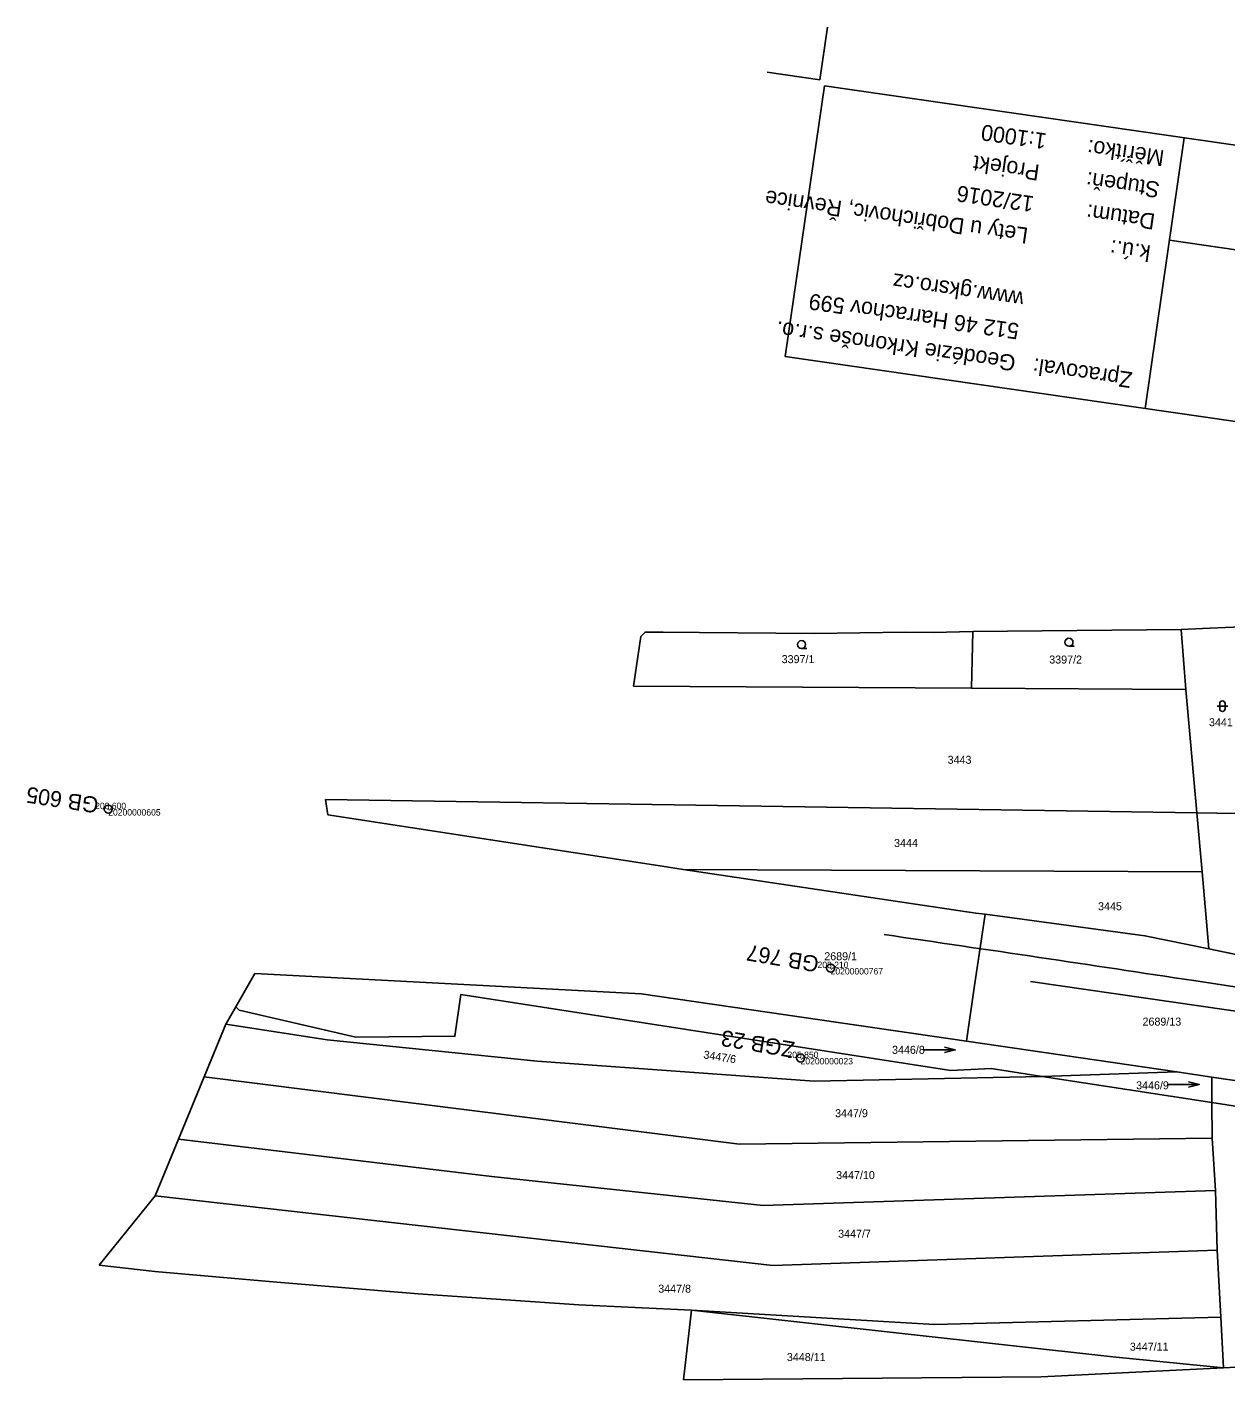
# Model space of a CAD drawing. Extents: x -757909 to -757266, y -1060303 to -1059942.
# Drawn here: x -757908.7 to -757684, y -1060195.2 to -1059941.6 of the extents above; entities that cross this region are included whole.
import ezdxf

# ---------------------------------------------------------------- set-up
doc = ezdxf.new("R2010")
doc.units = 0
for name, color, linetype in [('Legenda 1', 7, 'Continuous'), ('Vrstva 1', 7, 'Continuous'), ('Vrstva 53', 7, 'Continuous'), ('Vrstva 55', 7, 'Continuous'), ('Vrstva 57', 7, 'Continuous'), ('Vrstva 58', 7, 'Continuous'), ('Vrstva 60', 7, 'Continuous'), ('Vrstva 61', 7, 'Continuous'), ('Vrstva 63', 7, 'Continuous')]:
    doc.layers.add(name, color=color, linetype=linetype)

msp = doc.modelspace()

# ---------------------------------------------------------------- linework, layer by layer
at = {"layer": 'Legenda 1'}
for p, q in [((-757758.65, -1059941.6), (-757760.08, -1059951.5)), ((-757769.98, -1059950.07), (-757760.08, -1059951.5)), ((-757691.8, -1059962.36), (-757699.12, -1060013.09)), ((-757694.57, -1059981.56), (-757587.21, -1059997.05))]:
    msp.add_line(p, q, dxfattribs=at)
msp.add_lwpolyline([(-757759.23, -1059952.63), (-757584.43, -1059977.86), (-757591.76, -1060028.59), (-757766.56, -1060003.36)], close=True, dxfattribs=at)
at = {"layer": 'Vrstva 1'}
for p, q in [((-757429.32, -1060162.53), (-757720.62, -1060120.47)), ((-757665.26, -1060124.05), (-757689.98, -1060120.32))]:
    msp.add_line(p, q, dxfattribs=at)
msp.add_arc((-759559.14, -1072479.78), 12500, 81.400126, 81.669213, dxfattribs=at)
at = {"layer": 'Vrstva 53'}
for points in [[(-757852.31, -1060089.26), (-757789.66, -1060098.89), (-757785.7, -1060099.48), (-757730.83, -1060107.66), (-757729.12, -1060107.89), (-757699.16, -1060111.9), (-757687.19, -1060114.38), (-757639.93, -1060124.17), (-757624.54, -1060126.42), (-757624.32, -1060124.22), (-757612.89, -1060124.84), (-757606.63, -1060125.23), (-757568.62, -1060130.44), (-757535.86, -1060133.35), (-757534.03, -1060136.19), (-757533.01, -1060136.32), (-757528.28, -1060137.03), (-757525.99, -1060137.35), (-757523.49, -1060137.59)], [(-757328.56, -1060183.46), (-757338.29, -1060184.85), (-757361.91, -1060181.63), (-757443.58, -1060171.99), (-757470.38, -1060167.04), (-757513.1, -1060164.5), (-757526.21, -1060162.71), (-757533.6, -1060161.43), (-757535.01, -1060161.18), (-757542.9, -1060160.49), (-757543.88, -1060160.4), (-757632.1, -1060146.3), (-757634.26, -1060145.96), (-757635.44, -1060145.86), (-757686.64, -1060138.39), (-757693.18, -1060137.43), (-757732.62, -1060131.67), (-757793.56, -1060122.78), (-757866, -1060118.97)]]:
    msp.add_lwpolyline(points, dxfattribs=at)
at = {"layer": 'Vrstva 55'}
for p, q in [((-757688.39, -1060054.34), (-757677.84, -1060053.89)), ((-757794.99, -1060065.12), (-757793.62, -1060055.81)), ((-757761.16, -1060055.23), (-757782.62, -1060055.08)), ((-757731.45, -1060054.87), (-757738.86, -1060055.09)), ((-757731.69, -1060065.52), (-757731.45, -1060054.87)), ((-757692.38, -1060054.51), (-757731.45, -1060054.87)), ((-757692.38, -1060054.51), (-757688.39, -1060054.34)), ((-757691.5, -1060065.78), (-757692.38, -1060054.51)), ((-757794.99, -1060065.12), (-757731.69, -1060065.52)), ((-757731.69, -1060065.52), (-757691.5, -1060065.78)), ((-757691.5, -1060065.78), (-757689.45, -1060088.87)), ((-757689.45, -1060088.87), (-757688.47, -1060099.93)), ((-757689.45, -1060088.87), (-757676.88, -1060089.06)), ((-757785.7, -1060099.48), (-757688.47, -1060099.93)), ((-757688.47, -1060099.93), (-757687.19, -1060114.38)), ((-757687.19, -1060114.38), (-757639.93, -1060124.17)), ((-757869.56, -1060125.23), (-757866, -1060118.97)), ((-757866, -1060118.97), (-757793.56, -1060122.78)), ((-757793.56, -1060122.78), (-757732.62, -1060131.67)), ((-757871.42, -1060128.49), (-757869.56, -1060125.23)), ((-757875.47, -1060138.34), (-757871.42, -1060128.49)), ((-757693.18, -1060137.43), (-757732.62, -1060131.67)), ((-757718.41, -1060138.26), (-757693.18, -1060137.43)), ((-757686.64, -1060138.39), (-757693.18, -1060137.43)), ((-757880.28, -1060150.04), (-757875.47, -1060138.34)), ((-757718.41, -1060138.26), (-757686.61, -1060143.18)), ((-757686.61, -1060143.18), (-757686.64, -1060138.39)), ((-757686.57, -1060149.86), (-757686.61, -1060143.18)), ((-757884.65, -1060160.67), (-757880.28, -1060150.04)), ((-757685.97, -1060159.64), (-757686.57, -1060149.86)), ((-757685.61, -1060170.82), (-757685.97, -1060159.64)), ((-757895.12, -1060173.65), (-757884.65, -1060160.67)), ((-757684.97, -1060183.38), (-757685.61, -1060170.82)), ((-757884.69, -1060174.86), (-757895.12, -1060173.65)), ((-757861.86, -1060176.83), (-757884.69, -1060174.86)), ((-757835.37, -1060179.05), (-757861.86, -1060176.83)), ((-757805.28, -1060181.09), (-757835.37, -1060179.05)), ((-757784.15, -1060182.07), (-757805.28, -1060181.09)), ((-757785.65, -1060195.16), (-757784.15, -1060182.07)), ((-757684.44, -1060192.89), (-757684.97, -1060183.38))]:
    msp.add_line(p, q, dxfattribs=at)
for points in [[(-757782.62, -1060055.08), (-757789.45, -1060055.02), (-757792.84, -1060054.99), (-757793.62, -1060055.81)], [(-757738.86, -1060055.09), (-757744.02, -1060055.04), (-757761.16, -1060055.23)], [(-757852.31, -1060089.26), (-757852.72, -1060086.39), (-757689.45, -1060088.87)], [(-757785.7, -1060099.48), (-757789.66, -1060098.89), (-757852.31, -1060089.26)], [(-757729.12, -1060107.89), (-757730.83, -1060107.66), (-757785.7, -1060099.48)], [(-757732.62, -1060131.67), (-757731.15, -1060121.69), (-757729.8, -1060112.49), (-757729.12, -1060107.89)], [(-757729.12, -1060107.89), (-757699.16, -1060111.9), (-757687.19, -1060114.38)], [(-757869.56, -1060125.23), (-757868.9, -1060125.84), (-757847.02, -1060130.94), (-757828.46, -1060130.73), (-757827.38, -1060122.93), (-757735.56, -1060137.19), (-757727.96, -1060136.79), (-757718.41, -1060138.26)], [(-757871.42, -1060128.49), (-757852.4, -1060131.41), (-757813.07, -1060135.44), (-757761.18, -1060139.17), (-757718.41, -1060138.26)], [(-757875.47, -1060138.34), (-757775.17, -1060150.97), (-757686.57, -1060149.86)], [(-757634.26, -1060145.96), (-757635.44, -1060145.86), (-757686.64, -1060138.39)], [(-757686.61, -1060143.18), (-757664.14, -1060146.65), (-757658.56, -1060153.53), (-757630.94, -1060158.73)], [(-757685.97, -1060159.64), (-757770.72, -1060162.45), (-757821.53, -1060157.03), (-757880.28, -1060150.04)], [(-757884.65, -1060160.67), (-757768.87, -1060173.68), (-757685.61, -1060170.82)], [(-757784.15, -1060182.07), (-757738.63, -1060184.76), (-757684.97, -1060183.38)], [(-757784.15, -1060182.07), (-757705.21, -1060190.84), (-757684.44, -1060192.89)], [(-757785.65, -1060195.16), (-757718.62, -1060194.56), (-757684.44, -1060192.89)], [(-757684.44, -1060192.89), (-757656.46, -1060191.47), (-757636.9, -1060190.98)]]:
    msp.add_lwpolyline(points, dxfattribs=at)
at = {"layer": 'Vrstva 58'}
for p, q in [((-757763.52, -1060058.08), (-757762.52, -1060058.08)), ((-757713.4, -1060057.66), (-757712.4, -1060057.66)), ((-757685.65, -1060068.88), (-757683.65, -1060068.88)), ((-757685.15, -1060068.38), (-757685.15, -1060069.38)), ((-757684.15, -1060068.38), (-757684.15, -1060069.38)), ((-757740.7, -1060133.31), (-757734.7, -1060133.31)), ((-757694.98, -1060139.78), (-757688.98, -1060139.78))]:
    msp.add_line(p, q, dxfattribs=at)
for points in [[(-757736.7, -1060132.81), (-757734.7, -1060133.31), (-757736.7, -1060133.81)], [(-757690.98, -1060139.28), (-757688.98, -1060139.78), (-757690.98, -1060140.28)]]:
    msp.add_lwpolyline(points, dxfattribs=at)
for centre in [(-757713.4, -1060056.91), (-757763.52, -1060057.33)]:
    msp.add_circle(centre, 0.75, dxfattribs=at)
for centre, start, end in [((-757684.65, -1060068.38), 0, 180), ((-757684.65, -1060069.38), 180, 0)]:
    msp.add_arc(centre, 0.5, start, end, dxfattribs=at)
at = {"layer": 'Vrstva 60'}
for p, q in [((-757893.44, -1060088.18), (-757893.44, -1060088.18)), ((-757758.07, -1060117.97), (-757758.07, -1060117.97)), ((-757763.7, -1060134.82), (-757763.7, -1060134.82))]:
    msp.add_line(p, q, dxfattribs=at)
at = {"layer": 'Vrstva 63'}
for p, q in [((-757893.44, -1060088.23), (-757893.44, -1060088.13)), ((-757758.07, -1060118.02), (-757758.07, -1060117.92)), ((-757763.7, -1060134.87), (-757763.7, -1060134.77))]:
    msp.add_line(p, q, dxfattribs=at)
for centre in [(-757893.44, -1060088.18), (-757758.07, -1060117.97), (-757763.7, -1060134.82)]:
    msp.add_circle(centre, 0.756, dxfattribs=at)

# ---------------------------------------------------------------- texts
at = {"layer": 'Legenda 1'}
for s, p in [('Měřítko:       1:1000', (-757695.4, -1059964.75)), ('Stupeň:        Projekt', (-757696.26, -1059970.69)), ('k.ú.:              Lety u Dobřichovic, Řevnice', (-757697.97, -1059982.57)), ('Datum:         12/2016', (-757697.11, -1059976.63)), ('                    www.gksro.cz', (-757699.68, -1059994.45)), ('                    512 46 Harrachov 599', (-757700.54, -1060000.38)), ('Zpracoval:   Geodézie Krkonoše s.r.o.', (-757701.4, -1060006.32))]:
    msp.add_text(s, height=3, rotation=171.7882, dxfattribs=at).set_placement(p)
at = {"layer": 'Vrstva 57'}
for s, p in [('3397/1', (-757767.24, -1060060.82)), ('3397/2', (-757717.1, -1060060.89)), ('3441', (-757687.17, -1060072.64)), ('3443', (-757736.14, -1060079.68)), ('3444', (-757746.18, -1060095.27)), ('3445', (-757707.95, -1060107.13)), ('2689/1', (-757759.26, -1060116.5)), ('2689/13', (-757699.62, -1060128.75)), ('3446/8', (-757746.56, -1060134.04)), ('3446/9', (-757700.82, -1060140.69)), ('3447/9', (-757757.23, -1060145.92)), ('3447/10', (-757757.04, -1060157.52)), ('3447/7', (-757756.66, -1060168.5)), ('3447/8', (-757790.37, -1060178.8)), ('3447/11', (-757701.99, -1060189.67)), ('3448/11', (-757766.26, -1060191.62))]:
    msp.add_text(s, height=1.5, dxfattribs=at).set_placement(p)
msp.add_text('3447/6', height=1.5, rotation=351, dxfattribs=at).set_placement((-757781.98, -1060134.88))
at = {"layer": 'Vrstva 60'}
for s, p in [('20200000605', (-757893.44, -1060089.38)), ('20200000767', (-757758.07, -1060119.17)), ('20200000023', (-757763.7, -1060136.02))]:
    msp.add_text(s, height=1.2, dxfattribs=at).set_placement(p)
at = {"layer": 'Vrstva 61'}
for s, p in [('208.600', (-757895.89, -1060088.18)), ('208.210', (-757760.52, -1060117.97)), ('205.850', (-757766.15, -1060134.82))]:
    msp.add_text(s, height=1.2, dxfattribs=at).set_placement(p)
at = {"layer": 'Vrstva 63'}
for s, rotation, p in [('GB 605', 171.2344, (-757895.08, -1060086.03)), ('GB 767', 170.282, (-757760.09, -1060115.84)), ('ZGB 23', 170.4777, (-757764.65, -1060131.85))]:
    msp.add_text(s, height=3, rotation=rotation, dxfattribs=at).set_placement(p)

doc.saveas('drawing.dxf')
